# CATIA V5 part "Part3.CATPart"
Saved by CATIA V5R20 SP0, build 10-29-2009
Part number: Part3
Bounding box of the stored display mesh (mm): x -55 to 55, y -4.813 to 119.812, z 0 to 279.808
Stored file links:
  C:\Users\YS\Desktop\독수리\Part3.CATPart
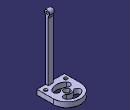
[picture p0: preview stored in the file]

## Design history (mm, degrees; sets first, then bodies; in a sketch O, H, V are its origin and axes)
Body1 (main body)
  Sketch1 on xy-plane, origin (0, 0, 0), H (1, 0, 0), V (0, 1, 0)
    line L1 (55, 65) -> (55, 0)
    line L2 (55, 0) -> (-55, 0)
    line L3 (-55, 0) -> (-55, 65)
    arc A1 centre (0, 65) radius 55 from (55, 65) to (-55, 65) ccw
    distance L1 L3 = 110
    radius A1 = 55
    length L1 = 65
    horizontal: L2 H
    vertical: L1 V, L3 V
    coincidence: L2 H
    symmetry: L3 L1 V
    tangency: A1 L1
  Pad1: profile Sketch1, direction (0, 0, 1), length 20
  Sketch2 on end face of Pad1, origin (0, 0, 20), H (1, 0, 0), V (0, 1, 0)
    circle A1 centre (0, 65) radius 12.5
    point P1 (0, 65)
    reference projected arc E1 centre (0, 65) radius 55 from (55, 65) to (-55, 65) ccw from edge [face of Pad1 from Sketch1.A1 | end face of Pad1]
    construction circle A2 centre (0, 65) radius 30
    construction line L1 (0, 65) -> (-48.7357, 113.7357)
    point P2 (-48.7357, 113.7357)
    point P3 (48.7357, 113.7357)
    point P4 (0, 65)
    construction line L2 (0, 65) -> (48.7357, 113.7357)
    construction arc A3 centre (0, 65) radius 30 from (21.2132, 86.2132) to (-21.2132, 86.2132) ccw
    point P5 (-21.2132, 86.2132)
    point P6 (21.2132, 86.2132)
    arc A4 centre (21.2132, 86.2132) radius 12.5 from (30.052, 95.052) to (12.3744, 77.3744) cw
    arc A5 centre (-21.2132, 86.2132) radius 12.5 from (-12.3744, 77.3744) to (-30.052, 95.052) cw
    arc A6 centre (0, 65) radius 17.5 from (12.3744, 77.3744) to (-12.3744, 77.3744) ccw
    arc A7 centre (0, 65) radius 42.5 from (-30.052, 95.052) to (30.052, 95.052) cw
    point P7 (12.3744, 77.3744)
    point P8 (-12.3744, 77.3744)
    point P9 (-30.052, 95.052)
    point P10 (30.052, 95.052)
    axis line L3 (0, 65) -> (99.8533, 65)
    point P12 (12.3744, 52.6256)
    point P13 (30.052, 34.948)
    arc A8 centre (21.2132, 43.7868) radius 12.5 from (30.052, 34.948) to (12.3744, 52.6256) ccw
    point P15 (-30.052, 34.948)
    point P16 (0, 65)
    arc A9 centre (0, 65) radius 42.5 from (-30.052, 34.948) to (30.052, 34.948) ccw
    point P17 (-12.3744, 52.6256)
    arc A10 centre (-21.2132, 43.7868) radius 12.5 from (-12.3744, 52.6256) to (-30.052, 34.948) ccw
    arc A11 centre (0, 65) radius 17.5 from (12.3744, 52.6256) to (-12.3744, 52.6256) cw
    radius A1 = 12.5
    radius A2 = 30
    angle L1 V = 45
    radius A5 = 12.5
    concentricity: A1 E1, A6 P4, A7 P4
    symmetry: P2 P3 V, P1 P4 V, L1 L2 V, P7 P12 L3, P10 P13 L3, A4 A8 L3, P9 P15 L3, P4 P16 L3, A7 A9 L3, P8 P17 L3, A5 A10 L3, A6 A11 L3
    coincidence: P5 L1, P5 A2, P6 L2
    tangency: A6 A5, A5 A7, A7 A4, A4 A6
    horizontal: L3 H
  Pocket1: profile Sketch2, direction (0, 0, -1), length 20
  Sketch3 on end face of Pad1, origin (0, 0, 20), H (1, 0, 0), V (0, 1, 0)
    point P1 (40, 20)
    reference projected line E1 (-55, 0) -> (55, 0) from edge [face of Pad1 from Sketch1.L2 | end face of Pad1]
    distance P1 V = 40
    distance P1 E1 = 20
  Sketch4 on end face of Pad1, origin (40, 20, 20), H (1, 0, 0), V (0, 1, 0)
    point P1 (0, 0)
    reference projected point E1 (0, 0) from Sketch3.P1
    coincidence: E1 P1
  Hole1: placed by Sketch4, at (40, 20, 20) direction (0, 0, -1), diameter 8, depth 20, countersink depth 3, countersink angle 90
  RectPattern1: of Hole1, direction 1 instances 2, spacing 80, along end face of Pad1 reversed
  Sketch5 on yz-plane, origin (0, 0, 0), H (0, 1, 0), V (0, 0, 1)
    line L1 (10, 253.4169) -> (10, 20)
    line L2 (10, 20) -> (0, 20)
    line L3 (0, 20) -> (0, 253.4169)
    reference projected line E1 (0, 0) -> (0, 20) from edge [face of Pad1 from Sketch1.L1 | face of Pad1 from Sketch1.L2]
    reference projected line E2 (0, 20) -> (65, 20) from edge [face of Pad1 from Sketch1.L1 | end face of Pad1]
    arc A1 centre (5, 270) radius 10 from (13.3333, 264.4723) to (-3.3333, 264.4723) ccw
    point P3 (5, 270)
    arc A2 centre (30, 253.4169) radius 20 from (13.3333, 264.4723) to (10, 253.4169) ccw
    arc A3 centre (-20, 253.4169) radius 20 from (-3.3333, 264.4723) to (0, 253.4169) cw
    distance L1 L3 = 10
    radius A1 = 10
    distance P3 L3 = 5
    radius A2 = 20
    radius A3 = 20
    distance P3 H = 270
    horizontal: L2 H
    vertical: L1 V, L3 V
    coincidence: L3 E1, L2 E2
    tangency: A2 L1, A2 A1, A3 L3, A3 A1
  Pad2: profile Sketch5, direction (1, 0, 0), length 20
  Sketch6 on end face of Pad2, origin (20, 0, 0), H (0, 1, 0), V (0, 0, 1)
    circle A1 centre (5, 270) radius 5
    reference projected arc E1 centre (5, 270) radius 10 from (13.3333, 264.4723) to (-3.3333, 264.4723) ccw from edge [face of Pad2 from Sketch5.A1 | end face of Pad2]
    radius A1 = 5
    concentricity: A1 E1
  Pocket2: profile Sketch6, direction (-1, 0, 0), length 20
